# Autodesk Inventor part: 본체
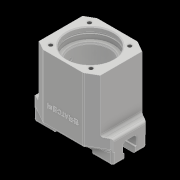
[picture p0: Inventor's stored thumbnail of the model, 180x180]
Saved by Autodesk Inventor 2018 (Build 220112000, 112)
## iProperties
Created: 2023-05
Part Number: 본체
Material: 일반
Document SubType Name: Modeling
Designer: home
Density: 1 g/cm^3
Appearance: 기본값
Author: home
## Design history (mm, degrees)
sketch "스케치1"
  geometry: L1 (-26, -35)-(26, -35); L2 (40, -26.917)-(40, 26.917); L3 (26, 35)-(-26, 35); L4 (-40, 26.917)-(-40, -26.917); L5 (-40, -35)-(40, 35); L6 (40, -35)-(-40, 35); L7 (-26, 35)-(-51, 20.566); L8 (26, 35)-(51, 20.566); L9 (-26, -35)-(-51, -20.566); L10 (26, -35)-(51, -20.566); L11 (51, -20)-(51, 20); L12 (-51, -20)-(-51, 20); 5 further points
  constraints: 24 end point, 8 point on line, 6 midpoint, 2 horizontal alignment, 2 parallel, 2 vertical, 1 horizontal, 1 perpendicular
  dimensions: "d0" = 80 distance between parallel lines of L2 L4; "d1" = 70 distance between parallel lines of L1 L3; "d4" = 52 distance of L3.end L3.start; "d5" = 52 distance of L1.end L1.start; "d6" = 26 horizontal distance of L1.start point (0, 0); "d7" = 26 horizontal distance of L3.end point (0, 0); "d8" = 60 deg angle of L7 L9; "d9" = 30 deg angle of L1 L9; "d10" = 60 deg angle of L8 L10; "d11" = 30 deg angle of L1 L10; "d12" = 71.1859 deg angle of L5 L8; "d13" = 11.1859 deg angle of L6 L8; "d14" = 43.31089 distance from line of point (0, 0) L8; "d15" = 40 distance from line of point (0, 0) L2; "d16" = 7 distance from line of L5.end L8; "d17" = 53.62178 distance from line of L6.start L8; "d18" = 33 distance from line of L6.end L8; "d19" = 93.62178 distance from line of L5.start L8; "d120" = 40 distance of L11.start L11.end; "d121" = 40 distance of L12.start L12.end; "d122" = 102 distance between parallel lines of L12 L11; "d123" = 51 distance from line of point (0, 0) L11
extrude "돌출1" new body sketch "스케치1" distance "d20" = 84; taper "d21" = 0 deg
sketch "스케치4"
  geometry: L1 (51, -69)-(-51, -69); L2 (-51, -69)-(-51, -99); L3 (-51, -99)-(51, -99); L4 (51, -99)-(51, -69); L5 (51, -69)-(-51, -99); L6 (-51, -69)-(51, -99); 3 further points
  constraints: 12 end point, 3 midpoint, 2 parallel, 1 horizontal, 1 perpendicular, 1 vertical alignment
  dimensions: "d23" = 102 distance between parallel lines of L2 L4; "d24" = 99 distance from line of point (0, 0) L3; "d25" = 30 distance between parallel lines of L3 L1
extrude "돌출2" join sketch "스케치4" stored distance "d26" = 44; taper "d27" = 0 deg
sketch "스케치5"
  geometry: L1 (-51, -99)-(-51, -69) reference; L2 (-51, -69)-(-40, -69) reference; L3 (-40, -84)-(-40, -69) reference; L4 (40, -84)-(-40, -84) reference; L5 (40, -69)-(40, -84) reference; L6 (40, 0)-(40, -69) reference; L7 (-40, 0)-(40, 0) reference; L8 (-40, -69)-(-40, 0) reference; L9 (51, -99)-(-51, -99) reference; L10 (51, -69)-(51, -99) reference; L11 (40, -69)-(51, -69) reference; L12 (25, -93)-(-25, -93); L13 (-25, -93)-(-25, -99); L14 (-25, -99)-(25, -99); L15 (25, -99)-(25, -93); L16 (25, -93)-(-25, -99); L17 (-25, -93)-(25, -99); 5 further points
  constraints: 12 end point, 6 midpoint, 2 parallel, 1 horizontal, 1 perpendicular, 1 vertical alignment
  dimensions: "d28" = 50 distance between parallel lines of L13 L15; "d29" = 6 distance between parallel lines of L12 L14
extrude "돌출3" cut sketch "스케치5" extent not by distance; stored distance "d30" = 44; taper "d31" = 0 deg
sketch "스케치6"
  geometry: L1 (-30, 44)-(0, 44) reference; L2 (0, 44)-(0, 0) reference; L3 (0, 0)-(-30, 0) reference; L4 (-30, 0)-(-30, 44) reference; L5 (-30, 14.8)-(-9, 14.8); L6 (-9, 14.8)-(-9, 29.2); L7 (-9, 29.2)-(-30, 29.2); L8 (-30, 29.2)-(-30, 14.8); L9 (-30, 14.8)-(-9, 29.2); L10 (-9, 14.8)-(-30, 29.2); L11 (-22, 13)-(-11, 13); L12 (-22, 31)-(-11, 31); L13 (-11, 13)-(-10.483, 14.8); L14 (-11, 31)-(-10.229, 29.2); L15 (-22, 13)-(-22.448, 14.8); L16 (-22, 31)-(-22.215, 29.2); 4 further points
  constraints: 24 end point, 5 midpoint, 4 point on line, 3 horizontal, 2 parallel, 1 horizontal alignment, 1 perpendicular
  dimensions: "d32" = 21 distance of L7.end L6.end; "d33" = 14.4 distance of L6.end L5.end; "d34" = 11 distance of L12.start L12.end; "d35" = 11 distance of L11.start L11.end; "d36" = 8 horizontal distance of L5.start L11.start; "d37" = 8 distance from line of L4 L12.start; "d38" = 18 distance between parallel lines of L12 L11; "d39" = 9 distance from line of point (-19.5, 22) L11; "d46" = 66.8015 deg angle of L3 L14; "d47" = 106.028 deg angle of L3 L13; "d48" = 83.1985 deg angle of L3 L16; "d49" = 103.972 deg angle of L3 L15
  node "절단 모서리 투영2"
extrude "돌출4" cut sketch "스케치6" extent not by distance; stored distance "d50" = 44; taper "d51" = 0 deg
sketch "스케치8"
  geometry: 2 further points
  constraints: 1 coincident
hole "구멍1" sketch "스케치8" at (0, 0) diameter "d53" = 60; stored, may be unused: countersink angle "d57" = 90 deg, drill point angle "d59" = 0 deg; dims "d54" = 6, "d55" = 4, "d56" = 2, "d58" = 14
node "작업 평면3"
sketch "스케치9"
  geometry: C1 r 31.5 at (0, 0); 1 further point
  constraints: 1 centre point, 1 coincident
  dimensions: "d61" = 63 diameter of C1
extrude "돌출5" cut sketch "스케치9" distance "d62" = 2.2; taper "d63" = 0 deg
node "작업 평면4"
sketch "스케치10"
  geometry: C1 r 25 at (0, 0); 1 further point
  constraints: 1 centre point, 1 coincident
  dimensions: "d65" = 50 diameter of C1
extrude "돌출6" cut sketch "스케치10" distance "d66" = 2; taper "d67" = 20 deg
node "작업 평면5"
sketch "스케치11"
  geometry: C1 r 25 at (0, 0); 1 further point
  constraints: 1 centre point, 1 coincident
  dimensions: "d69" = 50 diameter of C1
extrude "돌출7" cut sketch "스케치11" stored distance "d70" = 2; taper "d71" = 0 deg
hole "구멍2" diameter "d74" = 16; stored, may be unused: countersink angle "d78" = 90 deg, drill point angle "d80" = 0 deg; dims "d75" = 6, "d76" = 4, "d77" = 2, "d79" = 14, "d83" = 10, "d84" = 10
node "작업 평면6"
sketch "스케치12"
  geometry: C1 r 31.5 at (51, -22) reference; C2 r 10 at (51, -22); 1 further point
  constraints: 1 centre point, 1 coincident
  dimensions: "d82" = 20 diameter of C2
extrude "돌출8" cut sketch "스케치12" stored distance "d85" = 3.2; taper "d86" = 0 deg
node "작업 평면7"
sketch "스케치15"
  geometry: L1 (26, 25)-(-26, 25); L2 (-26, 25)-(-26, -25); L3 (-26, -25)-(26, -25); L4 (26, -25)-(26, 25); L5 (26, 25)-(-26, -25); L6 (-26, 25)-(26, -25); 5 further points
  constraints: 12 end point, 4 coincident, 2 midpoint, 2 parallel, 1 horizontal, 1 perpendicular
  dimensions: "d96" = 52 distance of L3.end L2.end; "d97" = 50 distance of L2.end L1.end
hole "구멍3" sketch "스케치15" at (26, -25), (26, 25), (-26, 25), (-26, -25) diameter "d98" = 4.917; stored, may be unused: countersink angle "d102" = 90 deg, drill point angle "d104" = 118 deg; dims "d99" = 12, "d100" = 4, "d101" = 2, "d103" = 14
sketch "스케치16"
  geometry: L1 (8, -37)-(42, -37); L2 (42, -37)-(42, -7); L3 (42, -7)-(8, -7); L4 (8, -7)-(8, -37); L5 (8, -37)-(42, -7); L6 (42, -37)-(8, -7); 5 further points
  constraints: 12 end point, 4 coincident, 2 midpoint, 2 parallel, 1 horizontal, 1 perpendicular
  dimensions: "d105" = 34 distance of L3.end L2.end; "d106" = 30 distance of L2.end L1.end
hole "구멍4" sketch "스케치16" at (8, -7), (8, -37), (42, -37), (42, -7) diameter "d107" = 2.459; stored, may be unused: countersink angle "d111" = 90 deg, drill point angle "d113" = 118 deg; dims "d108" = 6, "d109" = 4, "d110" = 2, "d112" = 8
sketch "스케치17"
  geometry: L1 (-26, 35)-(26, 35) reference; L2 (-40, 26.917)-(-26, 35) reference; L3 (-40, -26.917)-(-40, 26.917) reference; L4 (-26, -35)-(-40, -26.917) reference; L5 (26, -35)-(-26, -35) reference; L6 (40, -26.917)-(26, -35) reference; L7 (40, 26.917)-(40, -26.917) reference; L8 (26, 35)-(40, 26.917) reference; L9 (-38, -28.072)-(-38, 28.072); C1 r 2.458 at (-26, 25) reference; C2 r 2.458 at (26, -25) reference; C3 r 2.458 at (26, 25) reference; C4 r 2.458 at (-26, -25) reference; C5 r 30 at (0, 0) reference; 1 further point
  constraints: 2 end point, 2 point on line, 1 vertical
  dimensions: "d114" = 2 distance between parallel lines of L9 L3
extrude "돌출10" cut sketch "스케치17" distance "d115" = 64; taper "d116" = 0 deg
sketch "스케치22"
  geometry: L1 (-51, -9)-(51, -9) reference; L2 (51, -9)-(51, -22) reference; L3 (51, -22)-(40, -22) reference; L4 (40, -22)-(40, -26.917) reference; L5 (40, -26.917)-(26, -35) reference; L6 (26, -35)-(-26, -35) reference; L7 (-26, -35)-(-40, -26.917) reference; L8 (-40, -26.917)-(-40, -22) reference; L9 (40, -22)-(-40, -22) reference; L10 (-51, -22)-(-51, -9) reference; L11 (-40, -22)-(-51, -22) reference; L12 (-51, 22)-(-40, 22) reference; L13 (-40, 22)-(40, 22) reference; L14 (40, 26.917)-(40, 22) reference; L15 (26, 35)-(40, 26.917) reference; L16 (-26, 35)-(26, 35) reference; L17 (-40, 26.917)-(-26, 35) reference; L18 (-40, 22)-(-40, 26.917) reference; L19 (-51, 9)-(-51, 22) reference; L20 (51, 9)-(-51, 9) reference; L21 (51, 22)-(51, 9) reference; L22 (40, 22)-(51, 22) reference; L23 (-26, 35)-(-51, 20.566); L24 (-26, -35)-(26, -35) reference; L25 (-26, -35)-(-51, -20.566); L26 (26, -35)-(51, -20.566); L27 (26, 35)-(51, 20.566); L28 (-26, -35)-(-26, 35); L29 (26, -35)-(38, -28.072) reference; L30 (26, -35)-(26, 35); L31 (-51, -20.566)-(-51, 20.566); L32 (51, -20.566)-(51, 20.566); 1 further point
  constraints: 16 end point, 5 point on line, 2 parallel, 1 vertical
  dimensions: "d152" = 30 deg angle of L24 L25; "d153" = 30 deg angle of L6 L26; "d154" = 30 deg angle of L16 L27; "d155" = 30 deg angle of L16 L23
extrude "돌출12" join sketch "스케치22" stored distance "d156" = 64; taper "d157" = 0 deg
sketch "스케치14"
  geometry: L1 (-29, 0)-(29, 0); L2 (-29, -6)-(29, -6); L3 (29, 6)-(-29, 6); C1 r 12 at (0, 0); A1 r 6 centre (-29, 0) between (-29, 6) and (-29, -6); A2 r 6 centre (29, 0) between (29, -6) and (29, 6); 2 further points
  constraints: 8 end point, 4 point on circle, 4 tangent, 3 centre point, 2 coincident, 1 horizontal, 1 horizontal alignment, 1 midpoint, 1 parallel
  dimensions: "d91" = 24 diameter of C1; "d92" = 12 distance between parallel lines of L3 L2; "d93" = 58 distance of L1.start L1.end
extrude "돌출9" cut sketch "스케치14" distance "d94" = 30; taper "d95" = 0 deg
sketch "스케치23"
  geometry: L1 (41.028, -68.033)-(10.972, -68.033); L2 (10.972, -68.033)-(10.972, -49.967); L3 (10.972, -49.967)-(41.028, -49.967); L4 (41.028, -49.967)-(41.028, -68.033); L5 (-25, -99)-(1, -99) reference; 3 further points
  constraints: 2 midpoint, 1 parallel, 1 vertical alignment, 2 other
  dimensions: "d158" = 40 distance from line of L5 point (10.972, -59); "d159" = 49.03303 distance between parallel lines of L3 L5; "d160" = 30.05535 distance between parallel lines of L4 L2
feature "엠보싱1" sketch "스케치23" dims "d161" = 0.5, "d162" = 0
fillet "모깎기7" dims "d168" = 3
fillet "모깎기8" dims "d169" = 3
fillet "모깎기9" dims "d170" = 3
fillet "모깎기10" dims "d171" = 3
fillet "모깎기11" dims "d172" = 3
fillet "모깎기12" dims "d173" = 3
sketch "스케치24"
  geometry: L1 (0, 56.144)-(0, 0) reference; 5 further points
  constraints: 2 horizontal alignment, 2 midpoint
  dimensions: "d174" = 28 distance from line of L1 point (-28, 28.072); "d175" = 28 distance of point (-28, 28.072) point (-56, 28.072)
chamfer "모따기1" distance "d176" = 1; stored, may be unused: second distance "d177" = 2, angle "d178" = 45 deg
fillet "모깎기13" dims "d179" = 2
fillet "모깎기14" dims "d180" = 0.4
chamfer "모따기2" distance "d181" = 1; stored, may be unused: second distance "d182" = 2, angle "d183" = 45 deg
chamfer "모따기3" distance "d184" = 1; stored, may be unused: second distance "d185" = 2, angle "d186" = 45 deg
extrude "돌출13" cut sketch "스케치6" extent not by distance; stored distance "d187" = 10; taper "d188" = 0 deg
hole "구멍5" sketch "스케치24" diameter "d189" = 8; stored, may be unused: countersink angle "d195" = 90 deg, drill point angle "d197" = 118 deg; dims "d190" = 7.4, "d191" = 0.62479, "d192" = 7.985, "d193" = 4, "d194" = 2, "d196" = 11
sketch "스케치25"
  geometry: C1 r 4.224 at (-28, 28.072) reference; C2 r 4.224 at (-56, 28.072) reference; C3 r 2 at (-56, 28.072); C4 r 2 at (-28, 28.072); 1 further point
  constraints: 2 centre point, 2 coincident
  dimensions: "d198" = 4 diameter of C3; "d199" = 4 diameter of C4
extrude "돌출14" cut sketch "스케치25" distance "d200" = 20; taper "d201" = 0 deg
fillet "모깎기15" dims "d202" = 3
node "솔리드1"
node "투영된 루프1"
node "절단 모서리 투영1"
node "절단 모서리 투영3"
other parameters: "d40" = 30 deg, "d41" = 30 deg, "d60" = 6, "d64" = -2, "d68" = -45, "d81" = -35, "d90" = -99
